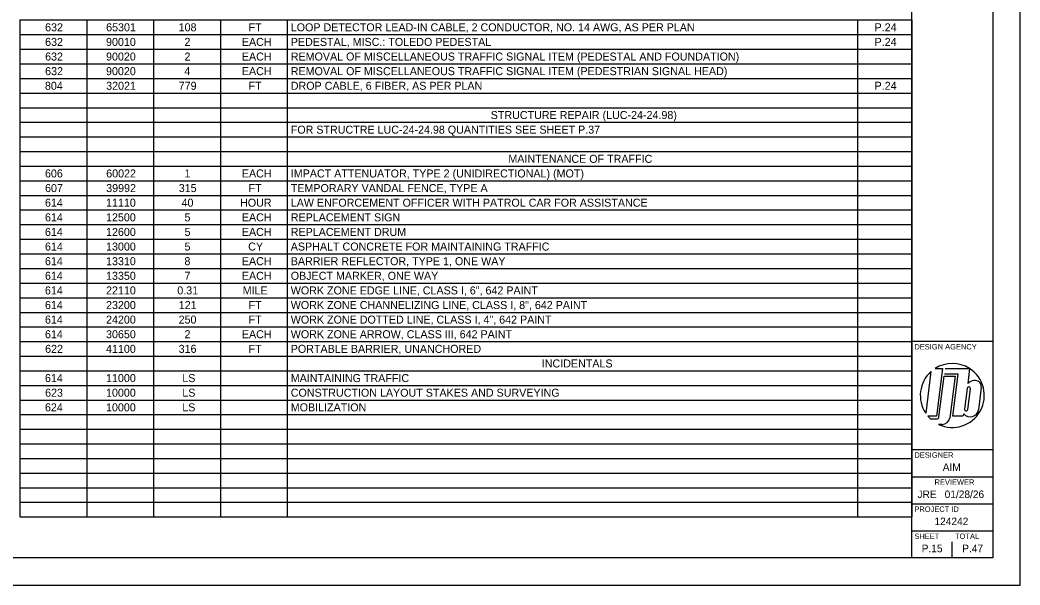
# Model space of a CAD drawing. Extents: x 0 to 34, y 0 to 22.
# Drawn here: x 15.54 to 34, y 0 to 10.43 of the extents above; entities that cross this region are included whole.
import ezdxf

# ---------------------------------------------------------------- set-up
doc = ezdxf.new("R2010")
doc.units = 0
for name, color, linetype in [('SH_Border', 7, 'Continuous'), ('SH_Cut_Line', 7, 'Continuous'), ('SH_Data', 7, 'Continuous'), ('SH_Text', 7, 'Continuous')]:
    doc.layers.add(name, color=color, linetype=linetype)

msp = doc.modelspace()

# ---------------------------------------------------------------- linework, layer by layer
at = {"layer": 'SH_Border'}
for p, q in [((32, 0.5), (32, 21.5)), ((32, 4.5), (33.5, 4.5)), ((32, 2.5), (33.5, 2.5)), ((32, 2), (33.5, 2)), ((32, 1.5), (33.5, 1.5)), ((32, 1), (33.5, 1))]:
    msp.add_line(p, q, dxfattribs=at)
msp.add_lwpolyline([(1.5, 21.5), (33.5, 21.5), (33.5, 0.5), (1.5, 0.5)], close=True, dxfattribs=at)
at = {"layer": 'SH_Cut_Line'}
msp.add_lwpolyline([(0, 0), (34, 0), (34, 22), (0, 22)], close=True, dxfattribs=at)
at = {"layer": 'SH_Data'}
for p, q in [((32.356, 3.94), (32.259, 3.171)), ((32.432, 3.998), (32.567, 3.998)), ((32.567, 3.998), (32.456, 3.118)), ((32.856, 3.896), (32.604, 3.896)), ((32.617, 4), (33.065, 4)), ((32.758, 3.118), (32.856, 3.896)), ((33.07, 3.996), (33.035, 3.72)), ((32.504, 3.104), (32.599, 3.855)), ((32.599, 3.855), (32.801, 3.855)), ((32.801, 3.855), (32.704, 3.089)), ((33.024, 3.631), (32.976, 3.25)), ((33.036, 3.243), (33.084, 3.624)), ((33.283, 3.648), (33.231, 3.237)), ((32.75, 3.5), (32.75, 3.5)), ((32.964, 3.161), (32.947, 3.118)), ((32.456, 3.118), (32.299, 3.118)), ((32.347, 3.068), (32.462, 3.068)), ((32.564, 2.966), (32.498, 2.966)), ((32.947, 3.118), (32.758, 3.118)), ((32.75, 0.5), (32.75, 0.8)), ((32.375, 0.675), (32.375, 0.675))]:
    msp.add_line(p, q, dxfattribs=at)
for centre, radius, start, end in [((32.75, 3.5), 0.591, 57.726, 122.5688), ((32.75, 3.5), 0.591, 131.8253, 213.7822), ((32.75, 3.5), 0.591, 244.7646, 57.1575), ((33.17, 3.586), 0.19, 105.9444, 135.0487), ((33.164, 3.6), 0.175, 66.6782, 105.4185), ((33.177, 3.669), 0.108, 349.2072, 58.7163), ((33.054, 3.628), 0.0301, 352.3298, 173.2777), ((33.081, 3.255), 0.151, 218.6264, 353.0883), ((33.006, 3.246), 0.0301, 172.3335, 353.274), ((32.75, 3.5), 0.591, 220.2786, 227.0158), ((32.462, 3.109), 0.0417, 270, 352.8038), ((32.564, 3.106), 0.141, 270, 352.8038)]:
    msp.add_arc(centre, radius, start, end, dxfattribs=at)
at = {"layer": 'SH_Text'}
for p, q in [((15.535, 10.434), (18.003, 10.434)), ((15.535, 10.434), (15.535, 10.164)), ((16.769, 10.434), (16.769, 10.164)), ((18.003, 10.434), (19.237, 10.434)), ((18.003, 10.434), (18.003, 10.164)), ((19.237, 10.434), (32, 10.434)), ((19.237, 10.434), (19.237, 10.164)), ((20.471, 10.434), (20.471, 10.164)), ((30.997, 10.434), (30.997, 10.164)), ((32, 10.434), (32, 10.164)), ((15.535, 10.164), (18.003, 10.164)), ((15.535, 10.164), (15.535, 9.354)), ((16.769, 10.164), (16.769, 9.354)), ((18.003, 10.164), (19.237, 10.164)), ((18.003, 10.164), (18.003, 9.354)), ((19.237, 10.164), (32, 10.164)), ((19.237, 10.164), (19.237, 9.354)), ((20.471, 10.164), (20.471, 9.354)), ((30.997, 10.164), (30.997, 9.354)), ((32, 10.164), (32, 9.354)), ((15.535, 9.894), (18.003, 9.894)), ((18.003, 9.894), (19.237, 9.894)), ((19.237, 9.894), (32, 9.894)), ((15.535, 9.624), (18.003, 9.624)), ((18.003, 9.624), (19.237, 9.624)), ((19.237, 9.624), (32, 9.624)), ((15.535, 9.354), (18.003, 9.354)), ((15.535, 9.354), (15.535, 8.814)), ((16.769, 9.354), (16.769, 8.814)), ((18.003, 9.354), (19.237, 9.354)), ((18.003, 9.354), (18.003, 8.814)), ((19.237, 9.354), (32, 9.354)), ((19.237, 9.354), (19.237, 8.814)), ((20.471, 9.354), (20.471, 8.814)), ((30.997, 9.354), (30.997, 8.814)), ((32, 9.354), (32, 8.814)), ((15.535, 9.084), (18.003, 9.084)), ((18.003, 9.084), (19.237, 9.084)), ((19.237, 9.084), (32, 9.084)), ((15.535, 8.814), (18.003, 8.814)), ((15.535, 8.814), (15.535, 8.004)), ((16.769, 8.814), (16.769, 8.004)), ((18.003, 8.814), (19.237, 8.814)), ((18.003, 8.814), (18.003, 8.004)), ((19.237, 8.814), (32, 8.814)), ((19.237, 8.814), (19.237, 8.004)), ((20.471, 8.814), (20.471, 8.004)), ((30.997, 8.814), (30.997, 8.004)), ((32, 8.814), (32, 8.004)), ((15.535, 8.544), (18.003, 8.544)), ((18.003, 8.544), (19.237, 8.544)), ((19.237, 8.544), (32, 8.544)), ((15.535, 8.274), (18.003, 8.274)), ((18.003, 8.274), (19.237, 8.274)), ((19.237, 8.274), (32, 8.274)), ((15.535, 8.004), (18.003, 8.004)), ((15.535, 8.004), (15.535, 7.465)), ((16.769, 8.004), (16.769, 7.465)), ((18.003, 8.004), (19.237, 8.004)), ((18.003, 8.004), (18.003, 7.465)), ((19.237, 8.004), (32, 8.004)), ((19.237, 8.004), (19.237, 7.465)), ((20.471, 8.004), (20.471, 7.465)), ((30.997, 8.004), (30.997, 7.465)), ((32, 8.004), (32, 7.465)), ((15.535, 7.735), (18.003, 7.735)), ((18.003, 7.735), (19.237, 7.735)), ((19.237, 7.735), (32, 7.735)), ((15.535, 7.465), (18.003, 7.465)), ((15.535, 7.465), (15.535, 6.655)), ((16.769, 7.465), (16.769, 6.655)), ((18.003, 7.465), (19.237, 7.465)), ((18.003, 7.465), (18.003, 6.655)), ((19.237, 7.465), (32, 7.465)), ((19.237, 7.465), (19.237, 6.655)), ((20.471, 7.465), (20.471, 6.655)), ((30.997, 7.465), (30.997, 6.655)), ((32, 7.465), (32, 6.655)), ((15.535, 7.195), (18.003, 7.195)), ((18.003, 7.195), (19.237, 7.195)), ((19.237, 7.195), (32, 7.195)), ((15.535, 6.925), (18.003, 6.925)), ((18.003, 6.925), (19.237, 6.925)), ((19.237, 6.925), (32, 6.925)), ((15.535, 6.655), (18.003, 6.655)), ((15.535, 6.655), (15.535, 5.575)), ((16.769, 6.655), (16.769, 5.575)), ((18.003, 6.655), (19.237, 6.655)), ((18.003, 6.655), (18.003, 5.575)), ((19.237, 6.655), (32, 6.655)), ((19.237, 6.655), (19.237, 5.575)), ((20.471, 6.655), (20.471, 5.575)), ((30.997, 6.655), (30.997, 5.575)), ((32, 6.655), (32, 5.575)), ((15.535, 6.385), (18.003, 6.385)), ((18.003, 6.385), (19.237, 6.385)), ((19.237, 6.385), (32, 6.385)), ((15.535, 6.115), (18.003, 6.115)), ((18.003, 6.115), (19.237, 6.115)), ((19.237, 6.115), (32, 6.115)), ((15.535, 5.845), (18.003, 5.845)), ((18.003, 5.845), (19.237, 5.845)), ((19.237, 5.845), (32, 5.845)), ((15.535, 5.575), (18.003, 5.575)), ((15.535, 5.575), (15.535, 5.305)), ((16.769, 5.575), (16.769, 5.305)), ((18.003, 5.575), (19.237, 5.575)), ((18.003, 5.575), (18.003, 5.305)), ((19.237, 5.575), (32, 5.575)), ((19.237, 5.575), (19.237, 5.305)), ((20.471, 5.575), (20.471, 5.305)), ((30.997, 5.575), (30.997, 5.305)), ((32, 5.575), (32, 5.305)), ((15.535, 5.305), (18.003, 5.305)), ((15.535, 5.305), (15.535, 4.226)), ((16.769, 5.305), (16.769, 4.226)), ((18.003, 5.305), (19.237, 5.305)), ((18.003, 5.305), (18.003, 4.226)), ((19.237, 5.305), (32, 5.305)), ((19.237, 5.305), (19.237, 4.226)), ((20.471, 5.305), (20.471, 4.226)), ((30.997, 5.305), (30.997, 4.226)), ((32, 5.305), (32, 4.226)), ((15.535, 5.035), (18.003, 5.035)), ((18.003, 5.035), (19.237, 5.035)), ((19.237, 5.035), (32, 5.035)), ((15.535, 4.765), (18.003, 4.765)), ((18.003, 4.765), (19.237, 4.765)), ((19.237, 4.765), (32, 4.765)), ((15.535, 4.496), (18.003, 4.496)), ((18.003, 4.496), (19.237, 4.496)), ((19.237, 4.496), (32, 4.496)), ((15.535, 4.226), (18.003, 4.226)), ((15.535, 4.226), (15.535, 3.956)), ((16.769, 4.226), (16.769, 3.956)), ((18.003, 4.226), (19.237, 4.226)), ((18.003, 4.226), (18.003, 3.956)), ((19.237, 4.226), (32, 4.226)), ((19.237, 4.226), (19.237, 3.956)), ((20.471, 4.226), (20.471, 3.956)), ((30.997, 4.226), (30.997, 3.956)), ((32, 4.226), (32, 3.956)), ((15.535, 3.956), (18.003, 3.956)), ((15.535, 3.956), (15.535, 2.876)), ((16.769, 3.956), (16.769, 2.876)), ((18.003, 3.956), (19.237, 3.956)), ((18.003, 3.956), (18.003, 2.876)), ((19.237, 3.956), (32, 3.956)), ((19.237, 3.956), (19.237, 2.876)), ((20.471, 3.956), (20.471, 2.876)), ((30.997, 3.956), (30.997, 2.876)), ((32, 3.956), (32, 2.876)), ((15.535, 3.686), (18.003, 3.686)), ((18.003, 3.686), (19.237, 3.686)), ((19.237, 3.686), (32, 3.686)), ((15.535, 3.416), (18.003, 3.416)), ((18.003, 3.416), (19.237, 3.416)), ((19.237, 3.416), (32, 3.416)), ((15.535, 3.146), (18.003, 3.146)), ((18.003, 3.146), (19.237, 3.146)), ((19.237, 3.146), (32, 3.146)), ((15.535, 2.876), (18.003, 2.876)), ((15.535, 2.876), (15.535, 2.606)), ((16.769, 2.876), (16.769, 2.606)), ((18.003, 2.876), (19.237, 2.876)), ((18.003, 2.876), (18.003, 2.606)), ((19.237, 2.876), (32, 2.876)), ((19.237, 2.876), (19.237, 2.606)), ((20.471, 2.876), (20.471, 2.606)), ((30.997, 2.876), (30.997, 2.606)), ((32, 2.876), (32, 2.606)), ((15.535, 2.606), (18.003, 2.606)), ((15.535, 2.606), (15.535, 1.527)), ((16.769, 2.606), (16.769, 1.527)), ((18.003, 2.606), (19.237, 2.606)), ((18.003, 2.606), (18.003, 1.527)), ((19.237, 2.606), (32, 2.606)), ((19.237, 2.606), (19.237, 1.527)), ((20.471, 2.606), (20.471, 1.527)), ((30.997, 2.606), (30.997, 1.527)), ((32, 2.606), (32, 1.527)), ((15.535, 2.336), (18.003, 2.336)), ((18.003, 2.336), (19.237, 2.336)), ((19.237, 2.336), (32, 2.336)), ((15.535, 2.066), (18.003, 2.066)), ((18.003, 2.066), (19.237, 2.066)), ((19.237, 2.066), (32, 2.066)), ((15.535, 1.796), (18.003, 1.796)), ((18.003, 1.796), (19.237, 1.796)), ((19.237, 1.796), (32, 1.796)), ((15.535, 1.527), (18.003, 1.527)), ((15.535, 1.527), (15.535, 1.257)), ((16.769, 1.527), (16.769, 1.257)), ((18.003, 1.527), (19.237, 1.527)), ((18.003, 1.527), (18.003, 1.257)), ((19.237, 1.527), (32, 1.527)), ((19.237, 1.527), (19.237, 1.257)), ((20.471, 1.527), (20.471, 1.257)), ((30.997, 1.527), (30.997, 1.257)), ((32, 1.527), (32, 1.257)), ((15.535, 1.257), (18.003, 1.257)), ((18.003, 1.257), (19.237, 1.257)), ((19.237, 1.257), (32, 1.257))]:
    msp.add_line(p, q, dxfattribs=at)

# ---------------------------------------------------------------- texts
at = {"layer": 'SH_Data'}
for s, height, p in [('DESIGN AGENCY', 0.1, (32.05, 4.35)), ('DESIGNER', 0.1, (32.05, 2.35)), ('AIM', 0.14, (32.573, 2.105)), ('REVIEWER', 0.1, (32.422, 1.85)), ('JRE', 0.14, (32.107, 1.605)), ('01/28/26', 0.14, (32.609, 1.605)), ('PROJECT ID', 0.1, (32.05, 1.35)), ('124242', 0.14, (32.421, 1.105)), ('SHEET', 0.1, (32.05, 0.85)), ('TOTAL', 0.1, (32.8, 0.85)), ('P.15', 0.14, (32.185, 0.605)), ('P.47', 0.14, (32.933, 0.605))]:
    msp.add_text(s, height=height, dxfattribs=at).set_placement(p)
at = {"layer": 'SH_Text'}
for s, height, p in [('632', 0.1478, (15.999, 10.225)), ('65301', 0.1478, (17.126, 10.225)), ('108', 0.1478, (18.465, 10.225)), ('FT', 0.1478, (19.756, 10.225)), ('LOOP DETECTOR LEAD-IN CABLE, 2 CONDUCTOR, NO. 14 AWG, AS PER PLAN', 0.14781, (20.535, 10.225)), ('P.24', 0.1478, (31.315, 10.225)), ('632', 0.1478, (15.999, 9.955)), ('90010', 0.1478, (17.124, 9.955)), ('2', 0.148, (18.573, 9.955)), ('EACH', 0.1478, (19.632, 9.955)), ('PEDESTAL, MISC.: TOLEDO PEDESTAL', 0.14781, (20.535, 9.955)), ('P.24', 0.1478, (31.315, 9.955)), ('632', 0.1478, (15.999, 9.685)), ('90020', 0.1478, (17.124, 9.685)), ('2', 0.148, (18.573, 9.685)), ('EACH', 0.1478, (19.632, 9.685)), ('REMOVAL OF MISCELLANEOUS TRAFFIC SIGNAL ITEM (PEDESTAL AND FOUNDATION)', 0.14781, (20.535, 9.685)), ('632', 0.1478, (15.999, 9.415)), ('90020', 0.1478, (17.124, 9.415)), ('4', 0.148, (18.57, 9.415)), ('EACH', 0.1478, (19.632, 9.415)), ('REMOVAL OF MISCELLANEOUS TRAFFIC SIGNAL ITEM (PEDESTRIAN SIGNAL HEAD)', 0.14781, (20.535, 9.415)), ('804', 0.1478, (15.996, 9.145)), ('32021', 0.1478, (17.126, 9.145)), ('779', 0.1478, (18.466, 9.145)), ('FT', 0.1478, (19.756, 9.145)), ('DROP CABLE, 6 FIBER, AS PER PLAN', 0.14781, (20.535, 9.145)), ('P.24', 0.1478, (31.315, 9.145)), ('STRUCTURE REPAIR (LUC-24-24.98)', 0.14781, (24.227, 8.605)), ('FOR STRUCTRE LUC-24-24.98 QUANTITIES SEE SHEET P.37', 0.14781, (20.535, 8.335)), ('MAINTENANCE OF TRAFFIC', 0.14781, (24.553, 7.796)), ('606', 0.1478, (15.997, 7.526)), ('60022', 0.1478, (17.127, 7.526)), ('1', 0.148, (18.573, 7.526)), ('EACH', 0.1478, (19.632, 7.526)), ('IMPACT ATTENUATOR, TYPE 2 (UNIDIRECTIONAL) (MOT)', 0.14781, (20.535, 7.526)), ('607', 0.1478, (15.998, 7.256)), ('39992', 0.1478, (17.127, 7.256)), ('315', 0.1478, (18.467, 7.256)), ('FT', 0.1478, (19.756, 7.256)), ('TEMPORARY VANDAL FENCE, TYPE A', 0.14781, (20.535, 7.256)), ('614', 0.1478, (15.996, 6.986)), ('11110', 0.1478, (17.124, 6.986)), ('40', 0.1478, (18.518, 6.986)), ('HOUR', 0.1478, (19.599, 6.986)), ('LAW ENFORCEMENT OFFICER WITH PATROL CAR FOR ASSISTANCE', 0.14781, (20.535, 6.986)), ('614', 0.1478, (15.996, 6.716)), ('12500', 0.1478, (17.124, 6.716)), ('5', 0.148, (18.573, 6.716)), ('EACH', 0.1478, (19.632, 6.716)), ('REPLACEMENT SIGN', 0.14781, (20.535, 6.716)), ('614', 0.1478, (15.996, 6.446)), ('12600', 0.1478, (17.124, 6.446)), ('5', 0.148, (18.573, 6.446)), ('EACH', 0.1478, (19.632, 6.446)), ('REPLACEMENT DRUM', 0.14781, (20.535, 6.446)), ('614', 0.1478, (15.996, 6.176)), ('13000', 0.1478, (17.124, 6.176)), ('5', 0.148, (18.573, 6.176)), ('CY', 0.1478, (19.749, 6.176)), ('ASPHALT CONCRETE FOR MAINTAINING TRAFFIC', 0.14781, (20.535, 6.176)), ('614', 0.1478, (15.996, 5.906)), ('13310', 0.1478, (17.124, 5.906)), ('8', 0.148, (18.571, 5.906)), ('EACH', 0.1478, (19.632, 5.906)), ('BARRIER REFLECTOR, TYPE 1, ONE WAY', 0.14781, (20.535, 5.906)), ('614', 0.1478, (15.996, 5.636)), ('13350', 0.1478, (17.124, 5.636)), ('7', 0.148, (18.572, 5.636)), ('EACH', 0.1478, (19.632, 5.636)), ('OBJECT MARKER, ONE WAY', 0.14781, (20.535, 5.636)), ('614', 0.1478, (15.996, 5.366)), ('22110', 0.1478, (17.124, 5.366)), ('0.31', 0.1478, (18.44, 5.366)), ('MILE', 0.1478, (19.648, 5.366)), ('WORK ZONE EDGE LINE, CLASS I, 6", 642 PAINT', 0.14781, (20.535, 5.366)), ('614', 0.1478, (15.996, 5.096)), ('23200', 0.1478, (17.124, 5.096)), ('121', 0.1478, (18.467, 5.096)), ('FT', 0.1478, (19.756, 5.096)), ('WORK ZONE CHANNELIZING LINE, CLASS I, 8", 642 PAINT', 0.14781, (20.535, 5.096)), ('614', 0.1478, (15.996, 4.827)), ('24200', 0.1478, (17.124, 4.827)), ('250', 0.1478, (18.464, 4.827)), ('FT', 0.1478, (19.756, 4.827)), ('WORK ZONE DOTTED LINE, CLASS I, 4", 642 PAINT', 0.14781, (20.535, 4.827)), ('614', 0.1478, (15.996, 4.557)), ('30650', 0.1478, (17.124, 4.557)), ('2', 0.148, (18.573, 4.557)), ('EACH', 0.1478, (19.632, 4.557)), ('WORK ZONE ARROW, CLASS III, 642 PAINT', 0.14781, (20.535, 4.557)), ('622', 0.1478, (15.999, 4.287)), ('41100', 0.1478, (17.124, 4.287)), ('316', 0.1478, (18.465, 4.287)), ('FT', 0.1478, (19.756, 4.287)), ('PORTABLE BARRIER, UNANCHORED', 0.14781, (20.535, 4.287)), ('INCIDENTALS', 0.14781, (25.17, 4.017)), ('614', 0.1478, (15.996, 3.747)), ('11000', 0.1478, (17.124, 3.747)), ('LS', 0.1478, (18.532, 3.747)), ('MAINTAINING TRAFFIC', 0.14781, (20.535, 3.747)), ('623', 0.1478, (15.999, 3.477)), ('10000', 0.1478, (17.124, 3.477)), ('LS', 0.1478, (18.532, 3.477)), ('CONSTRUCTION LAYOUT STAKES AND SURVEYING', 0.14781, (20.535, 3.477)), ('624', 0.1478, (15.996, 3.207)), ('10000', 0.1478, (17.124, 3.207)), ('LS', 0.1478, (18.532, 3.207)), ('MOBILIZATION', 0.14781, (20.535, 3.207))]:
    msp.add_text(s, height=height, dxfattribs=at).set_placement(p)

doc.saveas('drawing.dxf')
